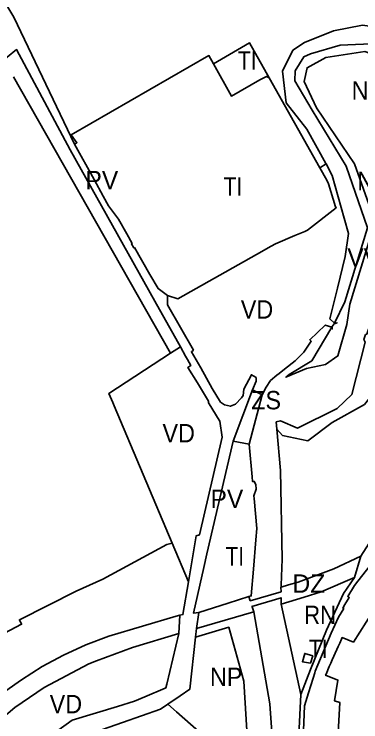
# Model space of a CAD drawing. Extents: x -650451 to -642268, y -1075216 to -1066610.
# Drawn here: x -646153 to -645870, y -1069586 to -1069009 of the extents above; entities that cross this region are included whole.
import ezdxf

# ---------------------------------------------------------------- set-up
doc = ezdxf.new("R2010")
doc.units = 0
doc.header["$LTSCALE"] = 6
doc.layers.add('1', color=7, linetype='Continuous', lineweight=35)
doc.layers.add('2', color=7, linetype='Continuous')
doc.layers.add('3', color=7, linetype='Continuous')

msp = doc.modelspace()

# ---------------------------------------------------------------- linework, layer by layer
at = {"layer": '1'}
for p, q in [((-646153.307, -1069059.947), (-646025.14, -1069285.394)), ((-645944.69, -1069060.7), (-645903.35, -1069134.27)), ((-645903.35, -1069134.27), (-645898.3, -1069130.96)), ((-646025.14, -1069285.394), (-646017.15, -1069280.19)), ((-645958.29, -1069315.44), (-645974.14, -1069357.22)), ((-645950.49, -1069319.46), (-645958.29, -1069315.44)), ((-645950.49, -1069319.46), (-645961.03, -1069359.69)), ((-645974.14, -1069357.22), (-645961.03, -1069359.69)), ((-646010.65, -1069471.91), (-646023.96, -1069440.34)), ((-645869.91, -1069451.02), (-645875.02, -1069468.52)), ((-645934.97, -1069490.31), (-645918.82, -1069563.81)), ((-645957.35, -1069496.35), (-646003.89, -1069510.07)), ((-646002.24, -1069496.95), (-646003.89, -1069510.07)), ((-646018.55, -1069514.14), (-646017.63, -1069499.08)), ((-646004.7, -1069517.16), (-646003.89, -1069510.07))]:
    msp.add_line(p, q, dxfattribs=at)
for points in [[(-646239.43, -1068865.79), (-646213.25, -1068917.87), (-646172.32, -1068979.11), (-646153.2, -1069011.21), (-646103.59, -1069114.91)], [(-645849.73, -1069020.52), (-645868.65, -1069017.82), (-645892.13, -1069022.51), (-645915.93, -1069031.93), (-645925.49, -1069038.22), (-645933.84, -1069055.44), (-645930.96, -1069081.23), (-645913.85, -1069102.71), (-645898.51, -1069130.56), (-645898.3, -1069130.96)], [(-645944.69, -1069060.7), (-645960.67, -1069032.26), (-645990.13, -1069049.3)], [(-645891.47, -1069261), (-645882.82, -1069243.58), (-645864.51, -1069183.09), (-645881.95, -1069132.83), (-645909.48, -1069087.11), (-645923.76, -1069063.17), (-645923.43, -1069055.15), (-645916.28, -1069043.56), (-645911, -1069041.05), (-645886.75, -1069034.06), (-645855.25, -1069032.83)], [(-646017.15, -1069280.19), (-646037.99, -1069242.88), (-646107, -1069119.41), (-646150.87, -1069037.64), (-646152.26, -1069038.76), (-646161.484, -1069046.228)], [(-646103.59, -1069114.91), (-646101.57, -1069113.74), (-646106.31, -1069107.25), (-645993.85, -1069042.59), (-645990.13, -1069049.3)], [(-645990.13, -1069049.3), (-645975.48, -1069075.71), (-645952.21, -1069062.4), (-645946.84, -1069059.58), (-645944.69, -1069060.7)], [(-645938.399, -1069347.452), (-645938.89, -1069341.56), (-645935.33, -1069340.64), (-645921.56, -1069346.6), (-645889.29, -1069330.52), (-645877.15, -1069319.06), (-645866.45, -1069276.32), (-645867.42, -1069274.21), (-645866.02, -1069270.26), (-645864.96, -1069269.78), (-645859.43, -1069254.08), (-645829.96, -1069154.65), (-645807.89, -1069094.51), (-645784.69, -1069060.74)], [(-645938.399, -1069347.452), (-645933.792, -1069352.53), (-645913.23, -1069356.892), (-645893.291, -1069341.938), (-645867.026, -1069327.317), (-645840.644, -1069294.052), (-645806.806, -1069193.112), (-645779.685, -1069122.296), (-645778.75, -1069108.98), (-645784.52, -1069075.66), (-645783.02, -1069061.84), (-645784.69, -1069060.74)], [(-646103.59, -1069114.91), (-646087.52, -1069143.7), (-646080.32, -1069157.3), (-646075.88, -1069165.21), (-646067.71, -1069176.01), (-646060.75, -1069188.02), (-646056.57, -1069196.03), (-646057.09, -1069196.32), (-646055.29, -1069199.5), (-646054.66, -1069199.23), (-646042, -1069221.33), (-646035.44, -1069232.74), (-646027.6, -1069238.4)], [(-645891.47, -1069261), (-645895.25, -1069257.41), (-645888.98, -1069232.44), (-645882.56, -1069206.54), (-645879.84, -1069187.64), (-645883.39, -1069175.24), (-645893.36, -1069140.52), (-645898.3, -1069130.96)], [(-646027.6, -1069238.4), (-646019.24, -1069241.19), (-645955.1, -1069204.88), (-645943.1, -1069198.09), (-645939.67, -1069196.28), (-645923.69, -1069189.44), (-645915.71, -1069186.03), (-645913.47, -1069185.07), (-645890.01, -1069166.73), (-645890.63, -1069165.94), (-645896.35, -1069147.12), (-645897.67, -1069144.37), (-645903.35, -1069134.27)], [(-645860.44, -1069185.14), (-645878.89, -1069245.47), (-645881.32, -1069262.01), (-645888.74, -1069287.69), (-645898.73, -1069294.78), (-645914.18, -1069297.97), (-645931.07, -1069305.08), (-645928.28, -1069302.75), (-645910, -1069291.57), (-645893.45, -1069264.1)], [(-646027.6, -1069238.4), (-646027.76, -1069246.09), (-646006.56, -1069282.94), (-646008.18, -1069284.24), (-646000.57, -1069297.38), (-645991.28, -1069314.21), (-645984.34, -1069325.39), (-645981.13, -1069327.68), (-645976.39, -1069328.73), (-645972.21, -1069326.99), (-645967.42, -1069321.83), (-645965.86, -1069319.83), (-645965.34, -1069314.71), (-645959.21, -1069303.06), (-645955.29, -1069305.35), (-645955.4, -1069308.28), (-645958.29, -1069315.44)], [(-645869.91, -1069451.02), (-645853.28, -1069425.27), (-645838.17, -1069409.28), (-645819.62, -1069389.66), (-645793.63, -1069362.15), (-645753.58, -1069323.64), (-645733.1, -1069308.58), (-645701.62, -1069274.36), (-645701.52, -1069256.86), (-645701.33, -1069247.86), (-645689, -1069254.5), (-645675.823, -1069254.48)], [(-645893.45, -1069264.1), (-645893.26, -1069265.61), (-645893.16, -1069263.64), (-645891.77, -1069261.46), (-645889.29, -1069260.66), (-645891.47, -1069261)], [(-645893.45, -1069264.1), (-645898.96, -1069262.45), (-645911.64, -1069274.48), (-645910.4, -1069275.66), (-645916.39, -1069284.67), (-645923.56, -1069291.6), (-645932.07, -1069298.43), (-645936.46, -1069301.94), (-645938.32, -1069303.37), (-645943.67, -1069307.84), (-645947.21, -1069313.26), (-645950.49, -1069319.46)], [(-646017.15, -1069280.19), (-646012.92, -1069287.88), (-646011.37, -1069290.71), (-646008.72, -1069295.53), (-646011.01, -1069297.08), (-646003.33, -1069309.64), (-645994.19, -1069324.6), (-645994.19, -1069326.07), (-645992.41, -1069328.97), (-645986.82, -1069338.04), (-645985, -1069340.98), (-645983.04, -1069354.04), (-646001.49, -1069433.59), (-646004.37, -1069434.58), (-646010.65, -1069471.91)], [(-646023.96, -1069440.34), (-646071.21, -1069328.33), (-646072.33, -1069325.68), (-646075.49, -1069318.19), (-646025.14, -1069285.394)], [(-645934.86, -1069476.27), (-645934.8, -1069474.71), (-645933.97, -1069453.52), (-645935.58, -1069381.24), (-645938.399, -1069347.452)], [(-645974.14, -1069357.22), (-645995.52, -1069449.1), (-645998.13, -1069460.33), (-646006.48, -1069497.53), (-646002.24, -1069496.95)], [(-645961.03, -1069359.69), (-645958.59, -1069386.32), (-645958.23, -1069390.23), (-645956.83, -1069390.08), (-645955.72, -1069392.55), (-645955.3, -1069396.28), (-645957.17, -1069401.86), (-645956.97, -1069404), (-645954.74, -1069428.36), (-645955.52, -1069437.7), (-645957.52, -1069461.75), (-645959.32, -1069483.43), (-645961.28, -1069484)], [(-646189.17, -1069528.74), (-646146.8, -1069506.6), (-646148.5, -1069503), (-646102.15, -1069479.49), (-646080.35, -1069469.89), (-646028.16, -1069441.58), (-646023.96, -1069440.34)], [(-645934.86, -1069476.27), (-645928.99, -1069474.55), (-645921.13, -1069472.25), (-645892.03, -1069461.43), (-645869.91, -1069451.02)], [(-645917.68, -1069620.16), (-645915.79, -1069573.09), (-645912.51, -1069562.49), (-645908.83, -1069550.61), (-645907.52, -1069546.36), (-645907.06, -1069544.88), (-645894.05, -1069513.84), (-645888.1, -1069500.82), (-645885.96, -1069497.27), (-645883.83, -1069493.87), (-645884.64, -1069493.36), (-645882.81, -1069490.44), (-645879.31, -1069484.84), (-645879.74, -1069484.57), (-645880.53, -1069484.08), (-645875.15, -1069474.99), (-645872.2, -1069471.51), (-645858.23, -1069453.6)], [(-645858.23, -1069453.6), (-645851.99, -1069459.64), (-645845.49, -1069463.04), (-645852.05, -1069475.74), (-645859.15, -1069489.47), (-645862.26, -1069495.5), (-645860.48, -1069496.62), (-645875.94, -1069521.19), (-645885.123, -1069517.463), (-645885.66, -1069518.71), (-645887.1, -1069521.95), (-645888.32, -1069524.69), (-645889.51, -1069527.34), (-645893.21, -1069535.65), (-645894.44, -1069538.39), (-645895.64, -1069541.08), (-645896.86, -1069543.82), (-645898.02, -1069546.92), (-645898.59, -1069548.21), (-645888.62, -1069552.14), (-645891.49, -1069568.99), (-645887.067, -1069570.398), (-645891.363, -1069649.02)], [(-645875.02, -1069468.52), (-645902.19, -1069480.13), (-645916.13, -1069484.55), (-645934.97, -1069490.31)], [(-645918.82, -1069563.81), (-645910.9, -1069543.64), (-645897.92, -1069511.49), (-645884.01, -1069481.56), (-645875.02, -1069468.52)], [(-646017.63, -1069499.08), (-646015.16, -1069498.74), (-646010.65, -1069471.91)], [(-645961.28, -1069484), (-645960.18, -1069487.45), (-645935.03, -1069480.02), (-645935.05, -1069476.32), (-645934.86, -1069476.27)], [(-645961.28, -1069484), (-645978.04, -1069489.3), (-646002.24, -1069496.95)], [(-645957.35, -1069496.35), (-645958.57, -1069492.51), (-645958.72, -1069492.05), (-645935, -1069485.04), (-645934.97, -1069490.31)], [(-645957.35, -1069496.35), (-645944.19, -1069571.66), (-645941.5, -1069609.76), (-645942.58, -1069624.73), (-645943.44, -1069636.76), (-645948.61, -1069657.43), (-645970.08, -1069692.61), (-646009.2, -1069734.98), (-646031.15, -1069747.2), (-646040.53, -1069755.58), (-646051.95, -1069771.98), (-646062.91, -1069794.85), (-646068.64, -1069840.94), (-646076.24, -1069876.52), (-646086.68, -1069900.4), (-646121.75, -1069950.24), (-646124.96, -1069959.99)], [(-646017.63, -1069499.08), (-646020.75, -1069500), (-646075.48, -1069516.38), (-646094.39, -1069523.34), (-646112.56, -1069531.78), (-646129.87, -1069541.19), (-646146.81, -1069551.97), (-646169.9, -1069568.04), (-646190.07, -1069586.48)], [(-646265.02, -1069696.43), (-646263.66, -1069694.78), (-646244.03, -1069670.61), (-646232.98, -1069657.69), (-646203.35, -1069617.55), (-646197.52, -1069612.3), (-646186.23, -1069623.04), (-646193.38, -1069608.83), (-646183.24, -1069600.22), (-646157.69, -1069579.08), (-646152.27, -1069574.59), (-646128.27, -1069558.17), (-646091.98, -1069538.88), (-646085.67, -1069536.53), (-646056.24, -1069525.54), (-646018.55, -1069514.14)], [(-646018.55, -1069514.14), (-646028.24, -1069555.37), (-646028.96, -1069558.45), (-646029.48, -1069558.67), (-646046.26, -1069565.81), (-646054.54, -1069569.34), (-646068.61, -1069573.63), (-646105.58, -1069584.91), (-646130.94, -1069603.1), (-646137.61, -1069608.96), (-646142.14, -1069612.9), (-646153.18, -1069622.24), (-646166.94, -1069635.16), (-646169.42, -1069637.65), (-646176.16, -1069644.04), (-646195.87, -1069662.74), (-646205.34, -1069680.08), (-646207.96, -1069697.21), (-646203.82, -1069728.79), (-646200.67, -1069752.88)], [(-645961.36, -1069630.05), (-645960.78, -1069628.91), (-645965.36, -1069552.99), (-645977.73, -1069509.11), (-646004.7, -1069517.16)], [(-646004.7, -1069517.16), (-646009.52, -1069559.6), (-646017.39, -1069564.94), (-646027.49, -1069571.79)], [(-645939.36, -1069710.47), (-645933.68, -1069680.28), (-645925.69, -1069644.69), (-645921.18, -1069613.78), (-645918.82, -1069563.81)], [(-646027.49, -1069571.79), (-646033.46, -1069575.84), (-646064.48, -1069586.72), (-646097.88, -1069598.43), (-646121.76, -1069613.94), (-646142.99, -1069631.85), (-646168.19, -1069660.3), (-646181.86, -1069675.73), (-646188.9, -1069692.13), (-646190.58, -1069708.64), (-646187.15, -1069740.55), (-646186.2, -1069749.43), (-646187.53, -1069750.63), (-646186.24, -1069769.06), (-646186.66, -1069775.09), (-646187.9, -1069781.01), (-646188.76, -1069783.97), (-646187.68, -1069788.27), (-646188.83, -1069794.63), (-646222.694, -1069834.722)], [(-646027.49, -1069571.79), (-646020.4, -1069578.04), (-645961.36, -1069630.05)]]:
    msp.add_lwpolyline(points, dxfattribs=at)
for points in [[(-645822.85, -1069058.8), (-645838.99, -1069049.31), (-645866.69, -1069039.37), (-645898.57, -1069044.24), (-645913.8, -1069052.51), (-645916.2, -1069063.8), (-645905.94, -1069085.11), (-645874.98, -1069131.01), (-645863.38, -1069163.79), (-645856.76, -1069163.17), (-645837.21, -1069112.54), (-645817.59, -1069069.6)], [(-645910.85, -1069538.44), (-645917.55, -1069537.16), (-645915.7, -1069530.41), (-645909.19, -1069532.46)]]:
    msp.add_lwpolyline(points, close=True, dxfattribs=at)

# ---------------------------------------------------------------- texts
at = {"layer": '2'}
for s, width, p in [('NP', 0.95, (-645872.804, -1069152.425)), ('TI', 0.85, (-645981.935, -1069156.834)), ('VD', 0.95, (-645967.854, -1069257.257)), ('ZS', 0.95, (-645959.36, -1069331.25)), ('VD', 0.95, (-646031.77, -1069358.226)), ('TI', 0.85, (-645980.353, -1069458.674)), ('TI', 0.85, (-645912.201, -1069534.128)), ('VD', 0.95, (-646123.847, -1069579.247))]:
    msp.add_text(s, height=15, dxfattribs=dict(at, width=width)).set_placement(p)
for s, p in [('VV', (-645880.931, -1069214.877)), ('PV', (-645992.583, -1069411.746)), ('DZ', (-645925.687, -1069480.928))]:
    msp.add_text(s, height=15, dxfattribs=at).set_placement(p)
at = {"layer": '3'}
for s, width, p in [('TI', 0.85, (-645970.125, -1069054.205)), ('NP', 0.95, (-645877.386, -1069078.485)), ('RN', 0.9, (-645916.133, -1069506.448)), ('NP', 0.95, (-645993.027, -1069556.988))]:
    msp.add_text(s, height=15, dxfattribs=dict(at, width=width)).set_placement(p)
msp.add_text('PV', height=15, dxfattribs=at).set_placement((-646094.651, -1069151.714))

doc.saveas('drawing.dxf')
